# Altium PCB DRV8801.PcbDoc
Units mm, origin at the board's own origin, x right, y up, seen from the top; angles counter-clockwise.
Board outline 30 x 20 mm, 2 copper layers (Top Layer, Bottom Layer); 12 components, 16 nets, 44 pads, 0 vias.
Unrouted connection lines stored in the file: 28.
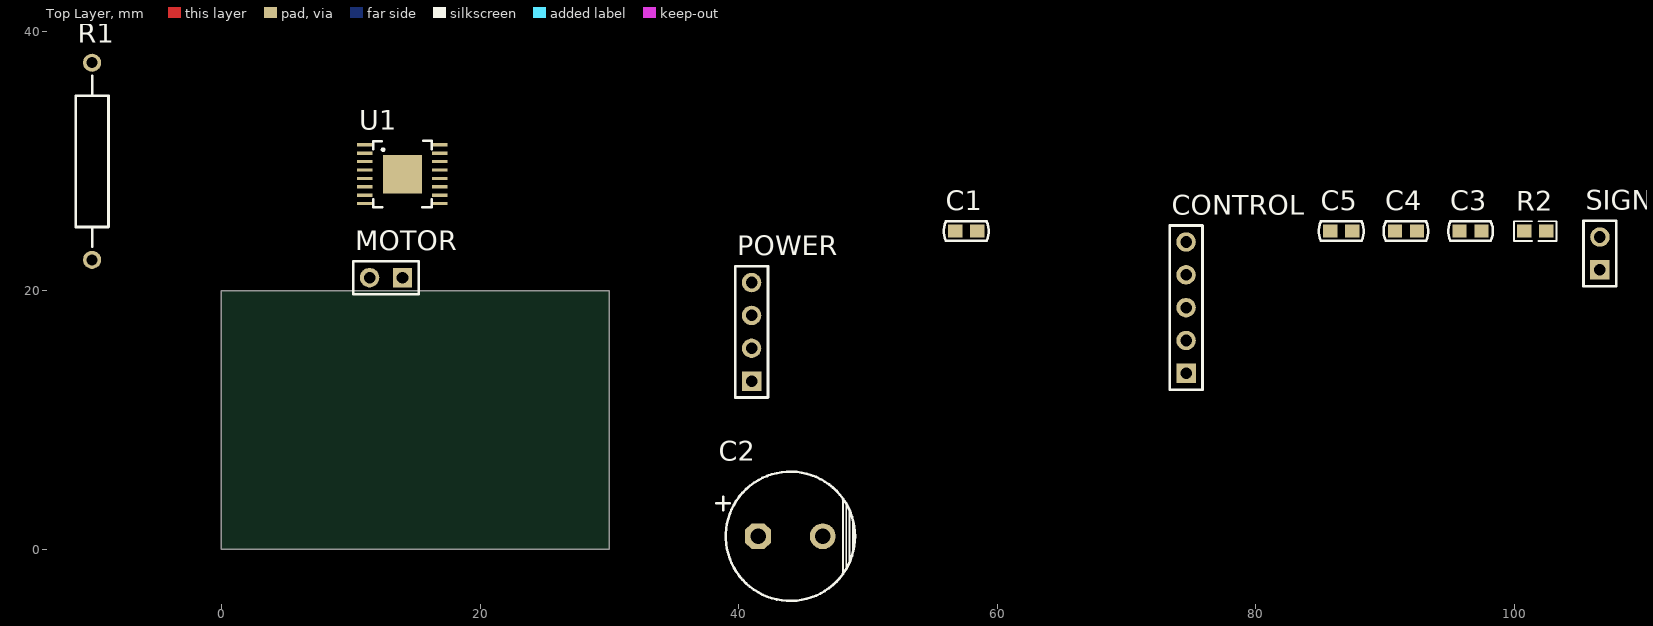
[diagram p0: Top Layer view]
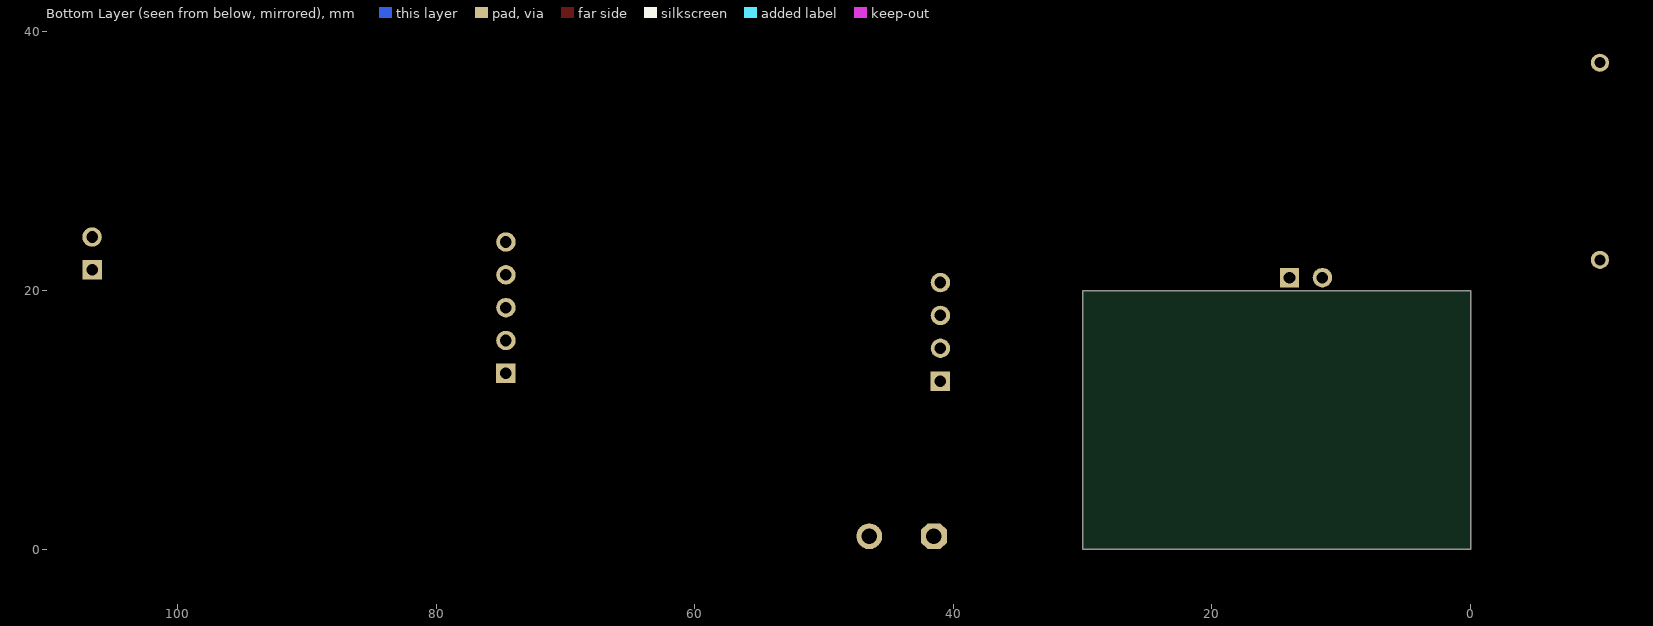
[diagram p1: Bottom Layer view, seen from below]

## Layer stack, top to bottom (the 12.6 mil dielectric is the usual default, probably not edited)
Top Solder: solder mask 0.0102, Solder Resist, Dk 3.5
Top Layer: signal copper 0.0356
Dielectric 1: dielectric 0.32, FR-4, Dk 4.8
Bottom Layer: signal copper 0.0356
Bottom Solder: solder mask 0.0102, Solder Resist, Dk 3.5

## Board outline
0,0 0,20 30,20 30,0 0,0

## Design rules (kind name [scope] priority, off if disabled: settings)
Clearance [All] p1: gap=0.254
PolygonConnect [All] p1: connectstyle=Relief reliefconductorwidth=0.254 reliefentries=4 polygonreliefangle="90 Angle" airgapwidth=0.254
RoutingVias [All] p1: holewidth=0.711 width=1.27 viastyle="Through Hole" minholewidth=0.711 minwidth=1.27 maxholewidth=0.711 maxwidth=1.27
SolderMaskExpansion [All] p1: expansion=0.102
Width [All] p1: maxlimit=0.254 minlimit=0.254 preferedwidth=0.254
30 further rules are at their usual default settings.

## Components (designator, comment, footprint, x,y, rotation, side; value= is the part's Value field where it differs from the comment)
C1 "Cap-S" C-0603 57.6,24.6 r0 top
C2 "Cap-Pol-ER" C-RB-5.0/10 44,1 r0 top
C3 "Cap-S" C-0603 96.6,24.6 r0 top
C4 "Cap-S" C-0603 91.6,24.6 r0 top
C5 "Cap-S" C-0603 86.6,24.6 r0 top
CONTROL "Header 5" HDR1X5 74.6,13.6 r90 top
MOTOR "Header 2" HDR2X1-2.54 14,21 r180 top
POWER "Header 4" HDR1X4 41,13 r90 top
R1 "Res Adj2" AXIAL-0.6 -10,30 r270 top
R2 "Res1" 0603-1 101.6,24.6 r0 top
SIGNAL "Header 2" HDR1X2 106.6,21.6 r90 top
U1 "DRV8801" HTSSOP16 14,29 r0 top

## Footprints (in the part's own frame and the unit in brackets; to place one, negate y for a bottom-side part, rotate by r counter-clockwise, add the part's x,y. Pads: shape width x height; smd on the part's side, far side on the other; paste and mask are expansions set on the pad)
0603-1 [mm] "0603带丝印"
  rect 1.1x1 smd: 1(-0.85,0) 2(0.85,0)
  silkscreen extent -1.65,-0.76 1.65,0.76, body extent -0.8,-0.4 0.8,0.4, height 0.3
AXIAL-0.6 [mm] "Axial Device, Thru-Hole; 2 Leads; 0.6 in Pin Spacing"
  round 1.4 hole 0.85: 1(-7.62,0) 2(7.62,0)
  silkscreen extent -6.6,-1.27 6.6,1.27
C-0603 [mm] "贴片电容"
  rect 1.1x1 smd: 1(-0.85,0) 2(0.85,0)
  silkscreen extent -1.73,-0.76 1.73,0.76, body extent -0.8,-0.4 0.8,0.4, height 0.3
C-RB-5.0/10 [mm] "插件电解电容"
  oct 2x2 hole 1.2: 1(-2.5,0)
  round 2 hole 1.2: 2(2.5,0)
  silkscreen extent -5.71,-5 5,5
HDR1X2 [mm] "Connector; Header; 2 Position"
  rect 1.5x1.5 hole 0.9: 1(0,0)
  round 1.5 hole 0.9: 2(2.54,0)
  silkscreen extent -1.27,-1.27 3.81,1.27
HDR1X4 [mm] "Connector; Header; 4 Position"
  rect 1.5x1.5 hole 0.9: 1(0,0)
  round 1.5 hole 0.9: 2(2.54,0) 3(5.08,0) 4(7.62,0)
  silkscreen extent -1.27,-1.27 8.89,1.27
HDR1X5 [mm] "Connector; Header; 5 Position"
  rect 1.5x1.5 hole 0.9: 1(0,0)
  round 1.5 hole 0.9: 2(2.54,0) 3(5.08,0) 4(7.62,0) 5(10.16,0)
  silkscreen extent -1.27,-1.27 11.43,1.27
HDR2X1-2.54 [mm] "2.54单排针排座"
  rect 1.5x1.5 hole 0.9: 1(0,0)
  round 1.5 hole 0.9: 2(2.54,0)
  silkscreen extent -1.27,-1.27 3.81,1.27, body extent -1.27,-1.27 3.81,1.27, height 8.54
HTSSOP16 [mm]
  rect 3x3 smd paste+0 mask+0.1: 0(0,0)
  rect 1.2x0.25 smd paste+0 mask+0.1: 1(-2.9,2.275) 2(-2.9,1.625) 3(-2.9,0.975) 4(-2.9,0.325) 5(-2.9,-0.325) 6(-2.9,-0.975) 7(-2.9,-1.625) 8(-2.9,-2.275) 9(2.9,-2.275) 10(2.9,-1.625) 11(2.9,-0.975) 12(2.9,-0.325) 13(2.9,0.325) 14(2.9,0.975) 15(2.9,1.625) 16(2.9,2.275)
  silkscreen extent -2.25,-2.55 2.25,2.58

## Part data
C1 C3 C4 C5: "贴片瓷片电容"
C2: "插件电解电容"
CONTROL: "Header, 5-Pin"
MOTOR: "接插件"
POWER: "Header, 4-Pin"
R1: "Variable Resistor"
R2: "贴片电阻"
SIGNAL: "Header, 2-Pin"

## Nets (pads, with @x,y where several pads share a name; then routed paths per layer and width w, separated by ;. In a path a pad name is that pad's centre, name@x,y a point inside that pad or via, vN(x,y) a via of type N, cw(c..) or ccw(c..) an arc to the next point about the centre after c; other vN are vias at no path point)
ENABLE: SIGNAL.1 U1.6
GND: C1.1 C2.2 C5.1 POWER.1 POWER.2 R1.1 U1.0 U1.4 U1.13
MODE1: CONTROL.4 U1.2
MODE2: CONTROL.3 U1.16
NetC3_2: C3.2 U1.14
NetC4_1: C4.1 U1.11
NetC4_2: C4.2 U1.12
NetMOTOR_1: MOTOR.1 U1.10
NetMOTOR_2: MOTOR.2 U1.7
NetR1_2: R1.2 U1.8
NetR2_1: R2.1 U1.15
NFAULT: CONTROL.5 U1.1
NSLEEP: CONTROL.2 U1.5
PHASE: SIGNAL.2 U1.3
VCC_11V: C1.2 C2.1 C3.1 POWER.3 POWER.4 U1.9
VPROPI: C5.2 CONTROL.1 R2.2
